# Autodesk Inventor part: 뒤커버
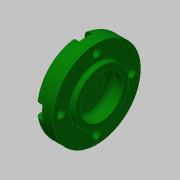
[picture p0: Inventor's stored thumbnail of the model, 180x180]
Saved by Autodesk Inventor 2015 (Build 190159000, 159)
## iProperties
Created: 2015-11
Part Number: 뒤커버
Material: 알루미늄 6061
Document SubType Name: Modeling
Designer: mduedu
Density: 1 g/cm^3
Appearance: 진녹색
Author: mduedu
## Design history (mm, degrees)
sketch "스케치1"
  geometry: L1 (-7, 0)-(7, 0); L2 (-7, 0)-(-7, 26); L3 (-7, 26)-(4, 26); L4 (4, 26)-(4, 16); L5 (4, 16)-(7, 16); L6 (7, 16)-(7, 0); 2 further points
  constraints: 12 end point, 3 perpendicular, 2 parallel, 1 coincident, 1 horizontal, 1 midpoint
  dimensions: "d0" = 14 distance of L1.start L1.end; "d1" = 52 diameter of L3 L1; "d2" = 3 distance of L4.end L5.end; "d3" = 32 diameter of L5 L1
revolve "회전1" sketch "스케치1" stored, may be unused: angle "d4" = 90 deg
hole "구멍1" diameter "d7" = 25; stored, may be unused: countersink angle "d11" = 90 deg, drill point angle "d13" = 0 deg; dims "d8" = 6, "d9" = 4, "d10" = 2, "d12" = 8, "d62" = 10, "d63" = 10
fillet "모깎기2" dims "d36" = 3
fillet "모깎기3" dims "d37" = 3
fillet "모깎기4" dims "d38" = 0.3
sketch "스케치3" dims "d61" = 42
  geometry: C1 r 26 at (0, 0) reference; 2 further points
  constraints: 2 vertical alignment, 1 coincident, 2 other
hole "구멍4" sketch "스케치3" at (0, -21) diameter "d44" = 4.5; stored, may be unused: countersink angle "d48" = 90 deg, drill point angle "d50" = 0 deg; dims "d45" = 6, "d46" = 8, "d47" = 4.6, "d49" = 8
sketch "스케치4"
  geometry: L1 (-4, 0)-(-4, -4.69); L2 (4, 0)-(4, -4.69); A1 r 4 centre (0, 0) between (3.614, -1.714) and (-3.614, -1.714) reference; A2 r 26 centre (0, 21) between (-4, -4.69) and (4, -4.69) reference; 1 further point
  constraints: 4 end point, 4 point on circle, 2 tangent, 1 parallel, 1 vertical
extrude "돌출1" cut sketch "스케치4" stored distance "d51" = 0; taper "d52" = 0 deg
node "솔리드1"
pattern_circular "원형 패턴1" dims angle "d54" = 360 deg
